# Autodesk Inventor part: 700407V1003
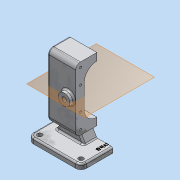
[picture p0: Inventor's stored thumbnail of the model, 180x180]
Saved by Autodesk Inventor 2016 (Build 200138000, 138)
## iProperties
Created: 2020-04
Part Number: 700407V1003
Material: 알루미늄 6061
Document SubType Name: Modeling
Designer: MIRAE
Density: 2.7 g/cm^3
Appearance: 알루미늄 - 평지
Mass: 1738.85 g
Surface Area: 885.412 cm^2
Volume: 644.02 cm^3
Author: MIRAE
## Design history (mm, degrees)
sketch "스케치1"
  geometry: L1 (70, -60)-(-30, -60); L2 (-30, -60)-(-30, 60); L3 (-30, 60)-(70, 60); L4 (70, 60)-(70, -60); L5 (0, -66.454)-(0, 77.18); 1 further point
  constraints: 10 end point, 2 parallel, 1 horizontal, 1 perpendicular, 1 point on line, 1 vertical
  dimensions: "d0" = 100 distance of L2.end L3.end; "d1" = 120 distance of L1.end L2.end; "d81" = 70 distance between parallel lines of L4 L5
extrude "돌출1" new body sketch "스케치1" distance "d2" = 10; taper "d3" = 0 deg
sketch "스케치2"
  geometry: 1 further point
node "작업 평면1"
sketch "스케치3"
  geometry: L1 (-150, 100)-(-30, 100); L2 (-30, 100)-(-30, 20); L3 (-30, 20)-(-150, 20); L4 (-150, 20)-(-150, 100); L5 (0, 120)-(0, 0) reference; L6 (0, 60)-(-156.135, 60)
  constraints: 10 end point, 2 parallel, 2 perpendicular, 1 horizontal, 1 other
  dimensions: "d5" = 150 distance between parallel lines of L5 L4; "d6" = 30 distance between parallel lines of L5 L2; "d7" = 80 distance between parallel lines of L3 L1
extrude "돌출2" join sketch "스케치3" distance "d8" = 53; taper "d9" = 0 deg
node "작업 평면2"
sketch "스케치4"
  geometry: L1 (30, 10)-(-70, 10) reference; L2 (0, 10)-(-11.547, 30); L3 (0, 30)-(-53, 30) reference; L4 (-53, 10)-(-41.453, 30); L5 (-41.453, 30)-(-11.547, 30); L6 (-53, 10)-(0, 10); L7 (-53, 150)-(-53, 30) reference; L8 (-53, 30)-(-53, 10); 1 further point
  constraints: 10 end point, 5 point on line, 2 collinear, 1 vertical
  dimensions: "d11" = 60 deg angle of L1 L4; "d12" = 60 deg angle of L1 L2; "d13" = 53 distance of L2.start L4.start
extrude "돌출3" join sketch "스케치4" distance "d14" = 48; taper "d15" = 0 deg
sketch "스케치5"
  geometry: L1 (-150, 100)-(-150, 20) reference; L2 (-30, 20)-(-30, 100) reference; L3 (-150, 20)-(-30, 20); L4 (-30, 20)-(-30, 100); L5 (-30, 100)-(-150, 100); L6 (-150, 100)-(-150, 20); L7 (-141, 91)-(-39, 91); L8 (-39, 91)-(-39, 29); L9 (-39, 29)-(-141, 29); L10 (-141, 29)-(-141, 91); 3 further points
  constraints: 16 end point, 4 parallel, 2 coincident, 2 perpendicular, 1 horizontal, 3 other
  dimensions: "d16" = 9 distance between parallel lines of L5 L7
hole "구멍1" sketch "스케치5" at (-141, 29), (-141, 91) diameter "d17" = 4.134; stored, may be unused: countersink angle "d21" = 90 deg, drill point angle "d23" = 118 deg; dims "d18" = 10, "d19" = 4, "d20" = 2, "d22" = 12
sketch "스케치6"
  geometry: L1 (-150, 100)-(-150, 20) reference; L2 (-150, 60)-(-30, 60); L3 (-30, 36)-(-30, 84) reference; L4 (-136, 60)-(-44, 60); L5 (-112, 36)-(-68, 36); L6 (-68, 84)-(-112, 84); A1 r 24 centre (-112, 60) between (-112, 84) and (-112, 36); A2 r 24 centre (-68, 60) between (-68, 36) and (-68, 84); 2 further points
  constraints: 10 end point, 6 point on circle, 4 point on line, 4 tangent, 3 midpoint, 2 centre point, 1 parallel
  dimensions: "d27" = 92 distance of L4.end L4.start; "d28" = 24 radius of A1; "d29" = 60 distance from line of L3 point (-90, 60)
extrude "돌출4" cut sketch "스케치6" distance "d30" = 29; taper "d31" = 0 deg
sketch "스케치7"
  geometry: L1 (-150, 100)-(-150, 20) reference; L2 (-150, 60)-(-30, 60); L3 (-30, 20)-(-30, 100) reference; L4 (-150, 20)-(-30, 20) reference; L5 (-90, 20)-(-90, 109.213); C1 r 12.5 at (-112, 60); C2 r 12.5 at (-68, 60); 1 further point
  constraints: 4 end point, 3 midpoint, 2 centre point, 2 point on line, 1 symmetric about line, 1 vertical
  dimensions: "d32" = 12.5 radius of C1; "d33" = 12.5 radius of C2; "d34" = 44 distance of C2.centre C1.centre
extrude "돌출5" cut sketch "스케치7" distance "d35" = 15; taper "d36" = 0 deg
sketch "스케치8"
  geometry: 1 further point
sketch "스케치9"
  geometry: C1 r 12.5 at (112, 60) reference; C2 r 19 at (112, 60); 1 further point
  constraints: 1 centre point, 1 coincident
  dimensions: "d37" = 19 radius of C2
extrude "돌출6" join sketch "스케치9" distance "d38" = 17; taper "d39" = 0 deg
sketch "스케치10"
  geometry: C1 r 8.5 at (0, 0); 1 further point
  constraints: 1 centre point
  dimensions: "d40" = 8.5 radius of C1
sketch "스케치11"
  geometry: C1 r 14 at (0, 0); 1 further point
  constraints: 1 centre point
  dimensions: "d41" = 14 radius of C1
extrude "돌출7" cut sketch "스케치11" distance "d42" = 7.3; taper "d43" = 0 deg
extrude "돌출8" cut sketch "스케치10" stored distance "d44" = 7.3; taper "d45" = 0 deg
sketch "스케치12"
  geometry: L1 (70, -60)-(-30, -60) reference; L2 (70, 60)-(-30, 60); L3 (-30, 60)-(-30, -60); L4 (-30, -60)-(70, -60); L5 (70, -60)-(70, 60); L6 (59, 49)-(-19, 49); L7 (-19, 49)-(-19, -49); L8 (-19, -49)-(59, -49); L9 (59, -49)-(59, 49); 5 further points
  constraints: 16 end point, 4 coincident, 4 parallel, 2 perpendicular, 1 horizontal, 3 other
  dimensions: "d46" = 11 distance between parallel lines of L5 L9
hole "구멍2" sketch "스케치12" at (59, 49), (-19, 49), (-19, -49), (59, -49) diameter "d47" = 9; stored, may be unused: countersink angle "d51" = 90 deg, drill point angle "d53" = 118 deg; dims "d48" = 10, "d49" = 4, "d50" = 2, "d52" = 12
sketch "스케치13"
  geometry: L1 (53, 38)-(53, 82) reference; L2 (53, 60)-(0, 60); L3 (0, 120)-(0, 0) reference; L4 (0, 0)-(53, 0) reference; L5 (41.453, 120)-(11.547, 120) reference; C1 r 11 at (39, 60); 1 further point
  constraints: 2 end point, 2 midpoint, 1 centre point
  dimensions: "d54" = 11 radius of C1; "d67" = 14 distance from line of L1 C1.centre
extrude "돌출9" join sketch "스케치13" distance "d55" = 8; taper "d56" = 0 deg
hole "구멍3" diameter "d59" = 8.376; stored, may be unused: countersink angle "d63" = 90 deg, drill point angle "d65" = 118 deg; dims "d57" = 10, "d58" = 10, "d60" = 20, "d61" = 4, "d62" = 2, "d64" = 27.3
fillet "모깎기1" dims "d66" = 9
fillet "모깎기2" dims "d68" = 3
fillet "모깎기3" dims "d72" = 0.5
fillet "모깎기4" dims "d73" = 10
chamfer "모따기2" distance "d74" = 1; stored, may be unused: second distance "d75" = 2, angle "d76" = 30 deg
fillet "모깎기5" dims "d77" = 3
fillet "모깎기6" dims "d78" = 3
fillet "모깎기7" dims "d79" = 3
fillet "모깎기8" dims "d80" = 3
sketch "스케치14"
  geometry: 1 further point
sketch "스케치15"
  geometry: L1 (30, 60)-(-70, 60); L2 (-70, 60)-(-70, -60); L3 (-70, -60)-(30, -60); L4 (30, -60)-(30, 60); 1 further point
  constraints: 8 end point, 2 parallel, 1 horizontal, 1 perpendicular
extrude "돌출10" cut sketch "스케치15" distance "d82" = 10; taper "d83" = 0 deg
sketch "스케치16"
  geometry: L1 (-83, 60)-(17, 60); L2 (17, 60)-(17, -60); L3 (17, -60)-(-83, -60); L4 (-83, -60)-(-83, 60); L5 (0, 0)-(-105.991, 0); L6 (17, -19)-(17, 19) reference
  constraints: 10 end point, 2 parallel, 2 perpendicular, 1 horizontal, 1 other
  dimensions: "d84" = 0 distance between parallel lines of L6 L2; "d85" = 100 distance between parallel lines of L2 L4; "d86" = 120 distance between parallel lines of L3 L1
extrude "돌출11" join sketch "스케치16" distance "d87" = 10; taper "d88" = 0 deg
fillet "모깎기9" dims "d89" = 10
sketch "스케치17"
  geometry: L1 (83, 60)-(-17, 60); L2 (-17, 60)-(-17, -60); L3 (-17, -60)-(83, -60); L4 (83, -60)-(83, 60); L5 (-6, 49)-(72, 49); L6 (72, 49)-(72, -49); L7 (72, -49)-(-6, -49); L8 (-6, -49)-(-6, 49); 5 further points
  constraints: 16 end point, 4 coincident, 4 parallel, 2 perpendicular, 1 horizontal, 3 other
  dimensions: "d90" = 11 distance between parallel lines of L1 L5
hole "구멍4" sketch "스케치17" at (-6, 49), (-6, -49), (72, -49), (72, 49) diameter "d91" = 9; stored, may be unused: countersink angle "d95" = 90 deg, drill point angle "d97" = 118 deg; dims "d92" = 20, "d93" = 4, "d94" = 2, "d96" = 27.3
fillet "모깎기10" dims "d98" = 3
sketch "스케치18"
  geometry: L1 (83, -50)-(83, 50) reference; L2 (-7, -60)-(73, -60) reference; 2 further points
  constraints: 1 other
  dimensions: "d101" = 10 distance from line of L1 point (73, 0); "d102" = 60 distance from line of L2 point (73, 0)
feature "엠보싱1" sketch "스케치18" dims "d99" = 0.5, "d100" = 0
node "작업 평면3"
chamfer "모따기3" distance "d103" = 0.7; stored, may be unused: second distance "d104" = 2, angle "d105" = 30 deg
feature "분할1"
node "솔리드1"
pattern_linear "직사각형 패턴1" dims "d26" = 29
mirror "대칭1"
mirror "대칭2"
other parameters: "d10" = 24
